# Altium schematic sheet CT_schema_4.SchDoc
size 321 x 309 mm
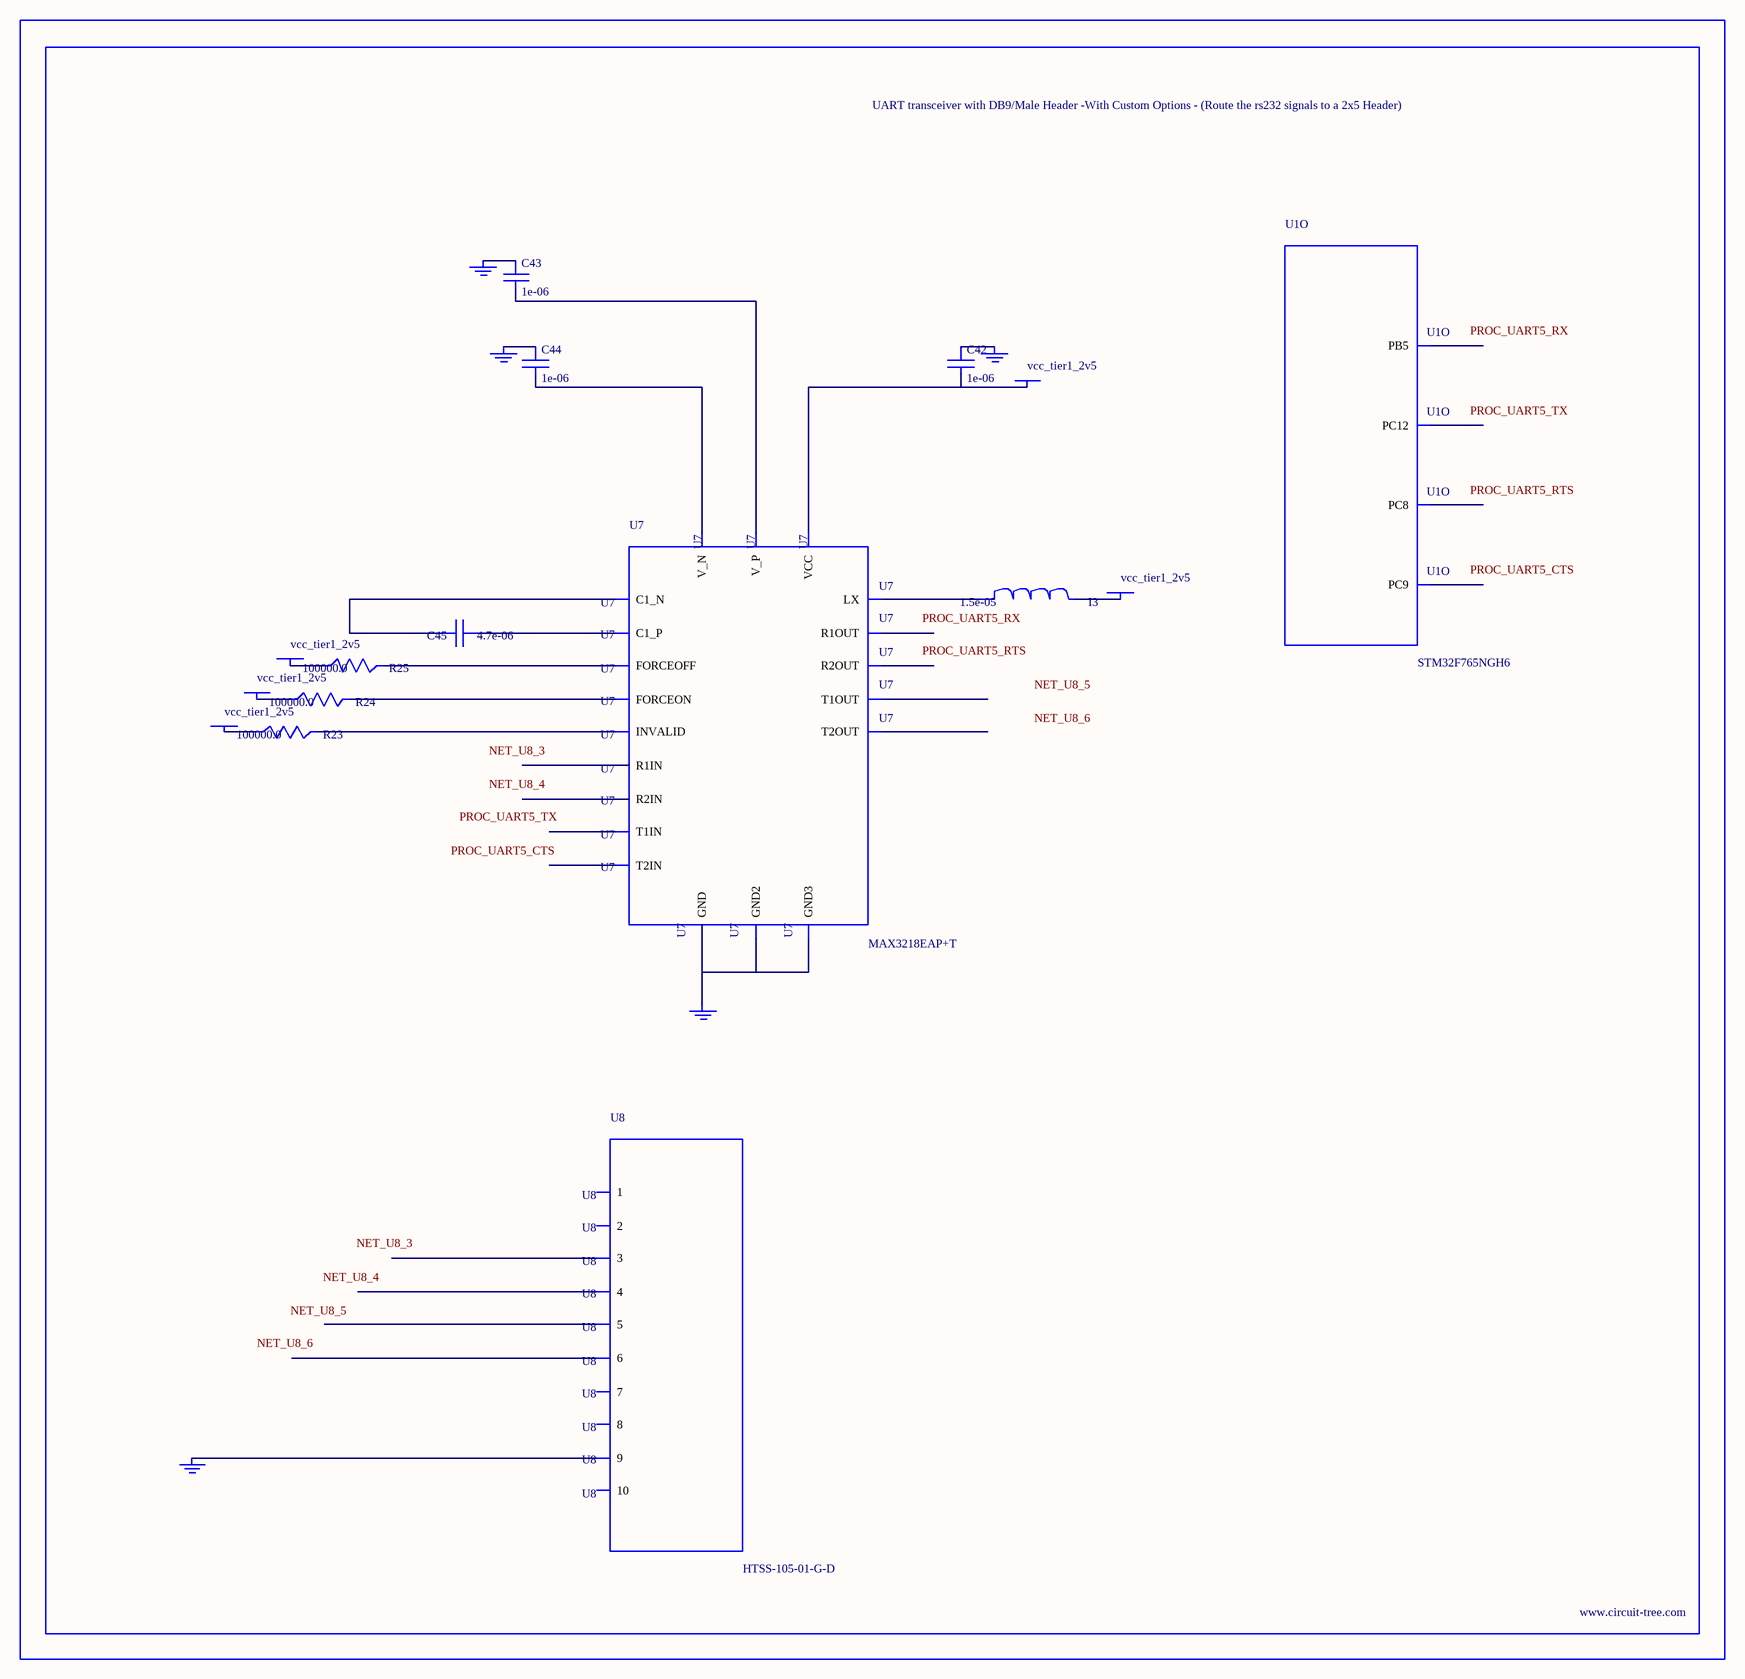
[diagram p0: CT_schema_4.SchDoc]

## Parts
BORDER3  (no value)
C42  1e-06  [C0603]
C43  1e-06  [C0603]
C44  1e-06  [C0603]
C45  4.7e-06  [C0805]
GND_INSTANCE_3_0  (no value)
GND_INSTANCE_3_1  (no value)
GND_INSTANCE_3_2  (no value)
GND_INSTANCE_3_3  (no value)
GND_INSTANCE_3_4  (no value)
I3  1.5e-05  [L1210]
POWER_INSTANCE_3_0  vcc_tier1_2v5
POWER_INSTANCE_3_1  vcc_tier1_2v5
POWER_INSTANCE_3_2  vcc_tier1_2v5
POWER_INSTANCE_3_3  vcc_tier1_2v5
POWER_INSTANCE_3_4  vcc_tier1_2v5
R23  100000.0  [R0603]
R24  100000.0  [R0603]
R25  100000.0  [R0603]
U1  STM32F765NGH6  [TFBGA216]  (part O of 18)
U7  MAX3218EAP+T  [SSOP-20]
U8  HTSS-105-01-G-D  [HTSS-105-01-G-D]

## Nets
NetC42_1: C42.1 GND_INSTANCE_3_0.0(GND)
NetC42_2: C42.2 POWER_INSTANCE_3_4.0(PWR) U7.6(VCC)
NetC43_1: C43.1 GND_INSTANCE_3_2.0(GND)
NetC43_2: C43.2 U7.19(V_P)
NetC44_1: C44.1 GND_INSTANCE_3_1.0(GND)
NetC44_2: C44.2 U7.15(V_N)
NetC45_1: C45.1 U7.18(C1_P)
NetC45_2: C45.2 U7.16(C1_N)
NetGND_INSTANCE_3_3_0: GND_INSTANCE_3_3.0(GND) U7.5(GND) U7.17(GND2) U7.20(GND3)
NetGND_INSTANCE_3_4_0: GND_INSTANCE_3_4.0(GND) U8.9
NetI3_1: I3.1 U7.1(LX)
NetI3_2: I3.2 POWER_INSTANCE_3_0.0(PWR)
NetPOWER_INSTANCE_3_1_0: POWER_INSTANCE_3_1.0(PWR) R23.1
NetPOWER_INSTANCE_3_2_0: POWER_INSTANCE_3_2.0(PWR) R24.1
NetPOWER_INSTANCE_3_3_0: POWER_INSTANCE_3_3.0(PWR) R25.1
NetR23_2: R23.2 U7.2(INVALID)
NetR24_2: R24.2 U7.3(FORCEON)
NetR25_2: R25.2 U7.4(FORCEOFF)

Not connected (* = marked no-connect by the designer): U1 A8(PB5) A12(PC12) F14(PC9) G14(PC8); U7 7(T1IN) 8(T2IN) 9(R1OUT) 10(R2OUT) 11(R2IN) 12(R1IN) 13(T2OUT) 14(T1OUT); U8 1 2 3 4 5 6 7 8 10

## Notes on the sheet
- Labels drawn without touching a wire or pin: NET_U8_3, NET_U8_4, NET_U8_5, NET_U8_6, PROC_UART5_CTS, PROC_UART5_RTS, PROC_UART5_RX, PROC_UART5_TX

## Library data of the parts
BORDER3 = BORDER_PAGE3
C42-C44 = C0603C105K3RACTU
C45 = C0805C475K4RACTU
GND_INSTANCE_3_0-GND_INSTANCE_3_4 = GND
I3 = L1210R150MDWIT
POWER_INSTANCE_3_0-POWER_INSTANCE_3_4 = PWR
R23-R25 = RC0603JR-07100KL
